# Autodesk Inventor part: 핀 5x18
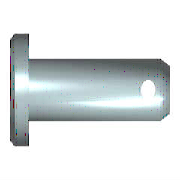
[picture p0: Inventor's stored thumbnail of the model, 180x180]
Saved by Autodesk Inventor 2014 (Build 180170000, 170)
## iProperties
Created: 2012-02
Part Number: 핀 5x18
Material: 강철
Description: 머리가 있는 클레비스 핀
Document SubType Name: Modeling
Standard: ISO 2341
Designer: test
Standard Revision: Second edition 1986-11-01
Standards Organization: ISO
Language: ko-KR
Size Designation: B - 5 x 18
Categories: <MemberInstance><Categories><Category DisplayName="조임쇠" InternalName="e4da775c-781d-43d5-af7c-5136215cf5a6" Mnemonic="FSTN"><Category DisplayName="핀" InternalNa
Density: 7.85 g/cm^3
Appearance: Steel
IsCustomPart: 1
Author: test
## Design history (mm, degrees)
sketch "스케치1"
  geometry: L1 (-1.6, 0)-(-1.6, 4); L2 (-1.6, 4)-(0, 4); L3 (0, 4)-(0, 2.5); L4 (0, 2.5)-(18, 2.5); L5 (18, 2.5)-(18, 0); L6 (-1.6, 0)-(18, 0); L7 (-4, 0)-(17, 0) reference; L8 (0, -0.98)-(0, 3.08) reference; C1 r 0.6 at (15.1, 0)
  constraints: 12 end point, 3 parallel, 2 collinear, 2 perpendicular, 1 centre point, 1 point on line, 1 vertical
  dimensions: "d0" = 5 diameter of L4 L6 (= NND); "d1" = 8 diameter of L2 L6 (= KOD); "d2" = 1.6 distance of L1.end L2.end (= KOH); "d3" = 18 distance of L3.end L4.end (= NLG); "d5" = 2.9 distance from line of L5 C1.centre (= DIST); "d6" = 1.2 diameter of C1 (= BOR)
revolve "본체" stored, may be unused: angle "d4" = 90 deg
extrude "구멍" cut sketch "스케치1" stored distance "d7" = 5 (= NND); taper "d8" = 0 deg
body "Solid1"
chamfer "모따기1" distance "d9" = 1 (= PHH2); stored, may be unused: angle "d10" = 45 deg (= FAWI2), second distance "d16" = 1 (= PHH2)
chamfer "모따기2" distance "d11" = 2 (= PHH1); stored, may be unused: angle "d12" = 30 deg (= FAWI1), second distance "d17" = 2 (= PHH1)
workaxis "Work Axis1"
workplane "Work Plane1"
other parameters: "PHH1" = 2 [user parameter; used in 2 equation terms], "PHH2" = 1 [user parameter; used in 2 equation terms], "KOD" = 8 [user parameter; used in 1 equation term], "KOH" = 1.6 [user parameter; used in 1 equation term], "NND" = 5 [user parameter; used in 2 equation terms], "FAWI1" = 30 deg [user parameter; used in 1 equation term], "FAWI2" = 45 deg [user parameter; used in 1 equation term], "DIST" = 2.9 [user parameter; used in 1 equation term], "BOR" = 1.2 [user parameter; used in 1 equation term], "NLG" = 18 [user parameter; used in 1 equation term], "d13" = 0, "d14" = 0, "d27" = 0, "d28" = 0, "d29" = 0, "d30" = 0, "d31" = 0
